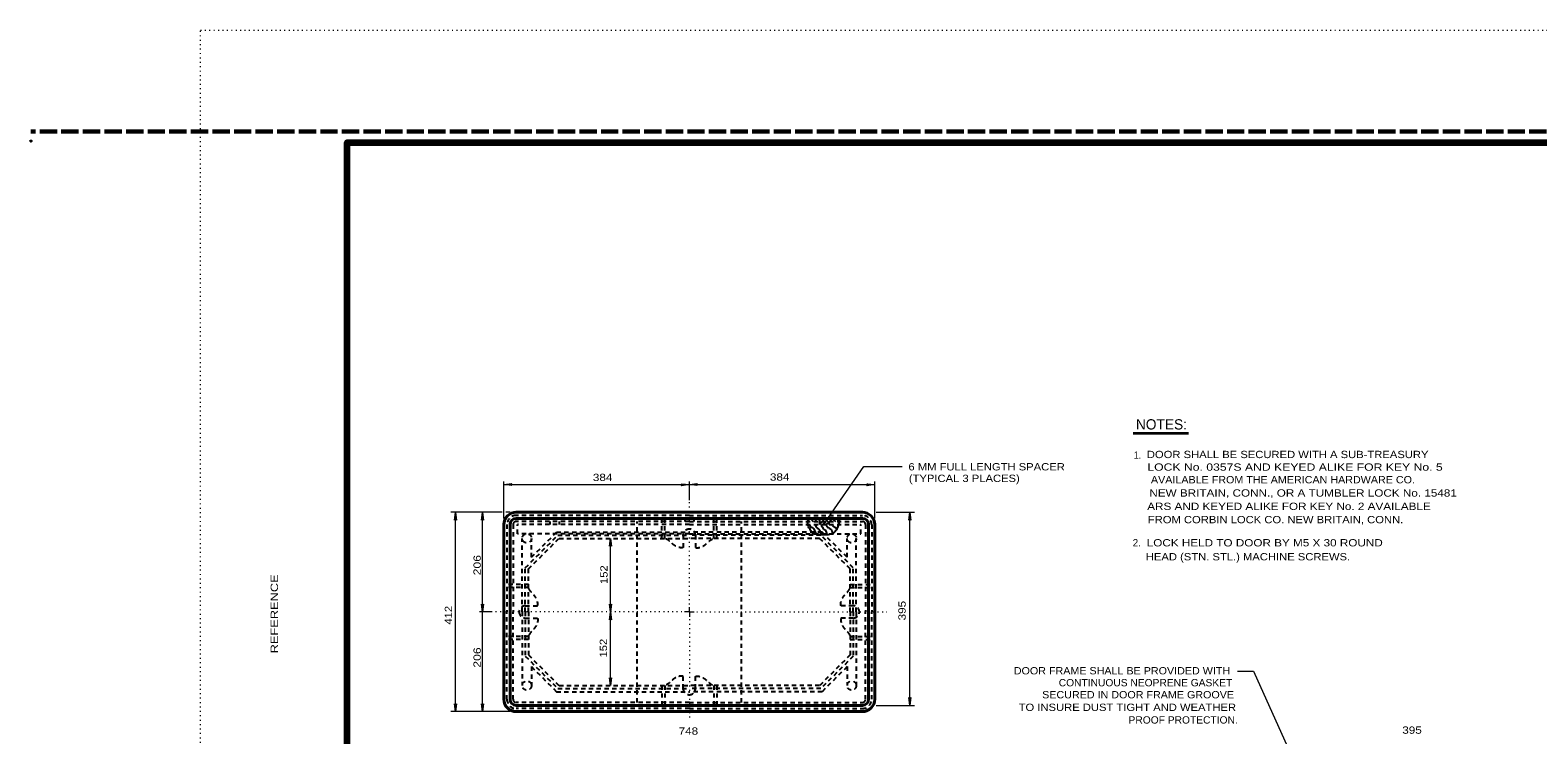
# Model space of a CAD drawing. Extents: x 312583 to 312854, y 144419 to 144597.
# Drawn here: x 312583.5 to 312740.6, y 144523.4 to 144596.8 of the extents above; entities that cross this region are included whole.
import ezdxf
from ezdxf.enums import TextEntityAlignment as Align

# ---------------------------------------------------------------- set-up
doc = ezdxf.new("R2010")
doc.units = 0
doc.header["$LTSCALE"] = 0.3
doc.header["$PDMODE"] = 32
doc.header["$PDSIZE"] = 0.15
for name, pattern in [('DOTTED', [1.5, 0.3, -1.2]), ('LONG_DASHED', [7.5, 6, -1.5]), ('SHORT_DASHED', [2.7, 1.5, -1.2])]:
    doc.linetypes.add(name, pattern=pattern)
for name, color, linetype, lineweight in [('1', 7, 'Continuous', 25), ('2', 7, 'Continuous', 13), ('63', 7, 'DOTTED', 13)]:
    doc.layers.add(name, color=color, linetype=linetype, lineweight=lineweight)

msp = doc.modelspace()

# ---------------------------------------------------------------- linework, layer by layer
at = {"layer": '1', "linetype": 'DOTTED', "lineweight": 13}
msp.add_line((312601.2, 144418.5846), (312601.2, 144596.7846), dxfattribs=at)
at = {"layer": '1', "linetype": 'LONG_DASHED', "lineweight": 60}
msp.add_line((312851.75, 144586.2246), (312583.526, 144586.2246), dxfattribs=at)
at = {"layer": '1', "lineweight": 40}
for p, q in [((312652.1571, 144546.558), (312634.1021, 144546.558)), ((312652.1571, 144545.914), (312634.1021, 144545.914)), ((312652.1571, 144546.558), (312670.2044, 144546.558)), ((312652.1571, 144545.914), (312670.2044, 144545.914)), ((312632.8294, 144545.2777), (312632.8294, 144536.1697)), ((312633.4658, 144545.2777), (312633.4658, 144536.1697)), ((312670.8408, 144545.2777), (312670.8408, 144536.1697)), ((312671.4771, 144545.2777), (312671.4771, 144536.1697)), ((312632.8294, 144527.0693), (312632.8294, 144536.1697)), ((312633.4658, 144527.0693), (312633.4658, 144536.1697)), ((312670.8408, 144527.0693), (312670.8408, 144536.1697)), ((312671.4771, 144527.0693), (312671.4771, 144536.1697)), ((312652.1571, 144526.433), (312634.1021, 144526.433)), ((312652.1571, 144525.789), (312634.1021, 144525.789)), ((312652.1571, 144526.433), (312670.2044, 144526.433)), ((312652.1571, 144525.789), (312670.2044, 144525.789))]:
    msp.add_line(p, q, dxfattribs=at)
at = {"layer": '1', "linetype": 'SHORT_DASHED'}
for p, q in [((312652.1571, 144546.236), (312634.1021, 144546.236)), ((312649.2821, 144543.8363), (312649.2821, 144546.236)), ((312649.5964, 144543.8363), (312649.5964, 144546.236)), ((312651.6741, 144545.914), (312651.6741, 144545.5997)), ((312652.1571, 144546.236), (312670.2044, 144546.236)), ((312652.6324, 144545.914), (312652.6324, 144545.5997)), ((312654.7101, 144543.8363), (312654.7101, 144546.236)), ((312655.0321, 144543.8363), (312655.0321, 144546.236)), ((312633.1438, 144545.2777), (312633.1438, 144536.1697)), ((312633.7878, 144545.2777), (312633.7878, 144536.1697)), ((312652.1571, 144545.5997), (312634.1021, 144545.5997)), ((312652.1571, 144545.2777), (312634.2631, 144545.2777)), ((312635.7044, 144541.866), (312638.3111, 144544.4803)), ((312637.6211, 144545.5997), (312637.6211, 144545.2777)), ((312638.3111, 144544.4803), (312652.1571, 144544.4803)), ((312638.5794, 144545.5997), (312638.5794, 144545.2777)), ((312646.7214, 144526.7473), (312646.7214, 144545.5997)), ((312652.1571, 144545.5997), (312670.2044, 144545.5997)), ((312652.1571, 144545.2777), (312670.0434, 144545.2777)), ((312665.9954, 144544.4803), (312652.1571, 144544.4803)), ((312657.5851, 144526.7473), (312657.5851, 144545.5997)), ((312665.7271, 144545.5997), (312665.7271, 144545.2777)), ((312668.6021, 144541.866), (312665.9954, 144544.4803)), ((312666.6854, 144545.5997), (312666.6854, 144545.2777)), ((312670.5188, 144545.2777), (312670.5188, 144536.1697)), ((312671.1628, 144545.2777), (312671.1628, 144536.1697)), ((312634.7461, 144536.1697), (312634.7461, 144543.8363)), ((312635.7044, 144541.866), (312635.7044, 144543.8363)), ((312638.5794, 144543.8363), (312652.1571, 144543.8363)), ((312651.5131, 144544.1583), (312651.5131, 144542.878)), ((312665.7271, 144543.8363), (312652.1571, 144543.8363)), ((312652.7934, 144544.1583), (312652.7934, 144542.878)), ((312668.6021, 144541.866), (312668.6021, 144543.8363)), ((312669.5604, 144536.1697), (312669.5604, 144543.8363)), ((312635.3824, 144539.0447), (312633.1438, 144539.0447)), ((312635.3824, 144538.7303), (312633.1438, 144538.7303)), ((312668.9241, 144539.0447), (312671.1628, 144539.0447)), ((312668.9241, 144538.7303), (312671.1628, 144538.7303)), ((312635.0604, 144536.8137), (312636.3408, 144536.8137)), ((312669.2461, 144536.8137), (312667.9658, 144536.8137)), ((312633.1438, 144527.0693), (312633.1438, 144536.1697)), ((312633.7878, 144527.0693), (312633.7878, 144536.1697)), ((312634.7461, 144536.1697), (312634.7461, 144528.503)), ((312635.0604, 144535.5333), (312636.3408, 144535.5333)), ((312669.2461, 144535.5333), (312667.9658, 144535.5333)), ((312669.5604, 144536.1697), (312669.5604, 144528.503)), ((312670.5188, 144527.0693), (312670.5188, 144536.1697)), ((312671.1628, 144527.0693), (312671.1628, 144536.1697)), ((312635.3824, 144533.6167), (312633.1438, 144533.6167)), ((312635.3824, 144533.2947), (312633.1438, 144533.2947)), ((312668.9241, 144533.6167), (312671.1628, 144533.6167)), ((312668.9241, 144533.2947), (312671.1628, 144533.2947)), ((312635.7044, 144530.4733), (312635.7044, 144528.503)), ((312635.7044, 144530.4733), (312638.3111, 144527.8667)), ((312668.6021, 144530.4733), (312665.9954, 144527.8667)), ((312668.6021, 144530.4733), (312668.6021, 144528.503)), ((312638.5794, 144528.503), (312652.1571, 144528.503)), ((312649.2821, 144528.503), (312649.2821, 144526.111)), ((312649.5964, 144528.503), (312649.5964, 144526.111)), ((312651.5131, 144528.1887), (312651.5131, 144529.4613)), ((312665.7271, 144528.503), (312652.1571, 144528.503)), ((312652.7934, 144528.1887), (312652.7934, 144529.4613)), ((312654.7101, 144528.503), (312654.7101, 144526.111)), ((312655.0321, 144528.503), (312655.0321, 144526.111)), ((312638.3111, 144527.8667), (312652.1571, 144527.8667)), ((312665.9954, 144527.8667), (312652.1571, 144527.8667)), ((312652.1571, 144526.7473), (312634.1021, 144526.7473)), ((312652.1571, 144526.111), (312634.1021, 144526.111)), ((312652.1571, 144526.7473), (312670.2044, 144526.7473)), ((312652.1571, 144526.111), (312670.2044, 144526.111))]:
    msp.add_line(p, q, dxfattribs=at)
at = {"layer": '1'}
for p, q in [((312664.5158, 144545.7837), (312664.6921, 144545.5997)), ((312664.7841, 144545.914), (312665.0754, 144545.5997)), ((312665.1674, 144545.914), (312665.4588, 144545.5997)), ((312665.5508, 144545.914), (312665.8421, 144545.5997)), ((312665.9341, 144545.914), (312666.2254, 144545.5997)), ((312666.3174, 144545.914), (312666.6088, 144545.5997)), ((312666.7008, 144545.914), (312666.9921, 144545.5997)), ((312667.0841, 144545.914), (312667.3754, 144545.5997)), ((312667.4674, 144545.914), (312667.7588, 144545.5997)), ((312665.7271, 144545.3083), (312666.0491, 144545.5997)), ((312666.0798, 144545.2777), (312666.4324, 144545.5997)), ((312666.4631, 144545.2777), (312666.6854, 144545.4847))]:
    msp.add_line(p, q, dxfattribs=at)
at = {"layer": '1', "lineweight": 158}
msp.add_lwpolyline([(312616.5, 144423.1446), (312616.5, 144585.0846), (312849, 144585.0846)], dxfattribs=at)
at = {"layer": '1', "linetype": 'SHORT_DASHED'}
for points in [[(312652.1571, 144544.3193), (312634.2631, 144544.3193), (312634.2631, 144545.2777)], [(312652.1571, 144544.3193), (312670.0434, 144544.3193), (312670.0434, 144545.2777)], [(312635.0604, 144536.1697), (312635.0604, 144540.7773), (312638.4414, 144544.1583), (312652.1571, 144544.1583)], [(312635.3824, 144536.1697), (312635.3824, 144540.647), (312638.5794, 144543.8363)], [(312669.2461, 144536.1697), (312669.2461, 144540.7773), (312665.8651, 144544.1583), (312652.1571, 144544.1583)], [(312668.9241, 144536.1697), (312668.9241, 144540.647), (312665.7271, 144543.8363)], [(312635.0604, 144536.1697), (312635.0604, 144531.5697), (312638.4414, 144528.1887), (312652.1571, 144528.1887)], [(312635.3824, 144536.1697), (312635.3824, 144531.7), (312638.5794, 144528.503)], [(312669.2461, 144536.1697), (312669.2461, 144531.5697), (312665.8651, 144528.1887), (312652.1571, 144528.1887)], [(312668.9241, 144536.1697), (312668.9241, 144531.7), (312665.7271, 144528.503)]]:
    msp.add_lwpolyline(points, dxfattribs=at)
for centre in [(312635.2227, 144543.8402), (312669.0838, 144543.8402), (312635.2227, 144528.5068), (312669.0838, 144528.5068)]:
    msp.add_circle(centre, 0.4792, dxfattribs=at)
at = {"layer": '1', "lineweight": 40}
for centre, radius, start, end in [((312634.1047, 144545.2777), 1.2778, 90, 180), ((312634.1047, 144545.2777), 0.6389, 90, 180), ((312670.2019, 144545.2777), 1.2778, 0, 90), ((312670.2019, 144545.2777), 0.6389, 0, 90), ((312634.1047, 144527.0693), 1.2778, 180, 270), ((312634.1047, 144527.0693), 0.6389, 180, 270), ((312670.2019, 144527.0693), 1.2778, 270, 0), ((312670.2019, 144527.0693), 0.6389, 270, 0)]:
    msp.add_arc(centre, radius, start, end, dxfattribs=at)
at = {"layer": '1', "linetype": 'SHORT_DASHED'}
for centre, radius, start, end in [((312634.1047, 144545.2777), 0.9583, 90, 180), ((312670.2019, 144545.2777), 0.9583, 0, 90), ((312634.1047, 144545.2777), 0.3194, 90, 180), ((312652.1533, 144544.1596), 0.6389, 90, 180), ((312652.1533, 144544.1596), 0.6389, 0, 90), ((312670.2019, 144545.2777), 0.3194, 0, 90), ((312635.063, 144536.1735), 0.6389, 90, 180), ((312669.2435, 144536.1735), 0.6389, 0, 90), ((312635.063, 144536.1735), 0.6389, 180, 270), ((312669.2435, 144536.1735), 0.6389, 270, 0), ((312634.1047, 144527.0693), 0.9583, 180, 270), ((312634.1047, 144527.0693), 0.3194, 180, 270), ((312652.1533, 144528.1874), 0.6389, 180, 270), ((312652.1533, 144528.1874), 0.6389, 270, 0), ((312670.2019, 144527.0693), 0.9583, 270, 0), ((312670.2019, 144527.0693), 0.3194, 270, 0)]:
    msp.add_arc(centre, radius, start, end, dxfattribs=at)
at = {"layer": '1'}
for points in [[(312667.7971, 144545.9063), (312667.7741, 144545.684), (312667.6591, 144545.1857), (312667.4904, 144544.741), (312667.1684, 144544.396), (312666.9078, 144544.281), (312666.3634, 144544.1967), (312665.8804, 144544.212), (312665.3974, 144544.2503), (312665.0601, 144544.35), (312664.7381, 144544.7487), (312664.5464, 144545.1627), (312664.5158, 144545.477), (312664.5311, 144545.6533), (312664.4698, 144545.9217)], [(312664.6691, 144545.2777), (312664.7074, 144545.1933), (312664.7841, 144545.0477), (312664.8914, 144544.994), (312665.0524, 144544.9173), (312665.1828, 144544.7103), (312665.2364, 144544.5723), (312665.2978, 144544.4113), (312665.3591, 144544.3193)], [(312665.2441, 144545.2623), (312665.2901, 144545.178), (312665.3821, 144545.0093), (312665.5354, 144544.8713), (312665.6658, 144544.7563), (312665.7578, 144544.5953), (312665.8114, 144544.4573), (312665.9034, 144544.3347)], [(312665.8574, 144545.27), (312665.8958, 144545.2087), (312665.9878, 144545.0553), (312666.0644, 144544.925), (312666.2254, 144544.7793), (312666.3634, 144544.6567), (312666.4248, 144544.488), (312666.4554, 144544.3807), (312666.4631, 144544.3193)], [(312666.4018, 144545.2777), (312666.4401, 144545.1473), (312666.5551, 144545.017), (312666.7238, 144544.9173), (312666.8848, 144544.81), (312667.0228, 144544.603), (312667.0458, 144544.5187), (312667.1224, 144544.3807)], [(312667.0381, 144545.27), (312667.0841, 144545.1933), (312667.1761, 144545.0937), (312667.3141, 144545.0093), (312667.4368, 144544.9403), (312667.5364, 144544.833)]]:
    msp.add_spline(points, degree=3, dxfattribs=at)
at = {"layer": '1', "linetype": 'SHORT_DASHED'}
for points in [[(312651.5131, 144542.878), (312651.2601, 144542.8627), (312650.8768, 144542.9623), (312650.5088, 144543.1693), (312650.1868, 144543.453), (312649.9414, 144543.66), (312649.5964, 144543.8363)], [(312652.7934, 144542.878), (312653.0464, 144542.8627), (312653.4298, 144542.9623), (312653.7978, 144543.1693), (312654.1198, 144543.453), (312654.3651, 144543.66), (312654.7101, 144543.8363)], [(312636.3408, 144536.8137), (312636.3561, 144537.0667), (312636.2641, 144537.45), (312636.0494, 144537.818), (312635.7734, 144538.14), (312635.5588, 144538.3853), (312635.3824, 144538.7303)], [(312667.9658, 144536.8137), (312667.9504, 144537.0667), (312668.0424, 144537.45), (312668.2571, 144537.818), (312668.5331, 144538.14), (312668.7478, 144538.3853), (312668.9241, 144538.7303)], [(312636.3408, 144535.5333), (312636.3561, 144535.2803), (312636.2641, 144534.897), (312636.0494, 144534.529), (312635.7734, 144534.207), (312635.5588, 144533.9617), (312635.3824, 144533.6167)], [(312667.9658, 144535.5333), (312667.9504, 144535.2803), (312668.0424, 144534.897), (312668.2571, 144534.529), (312668.5331, 144534.207), (312668.7478, 144533.9617), (312668.9241, 144533.6167)], [(312651.5131, 144529.4613), (312651.2601, 144529.4843), (312650.8768, 144529.3847), (312650.5088, 144529.1777), (312650.1868, 144528.894), (312649.9414, 144528.687), (312649.5964, 144528.503)], [(312652.7934, 144529.4613), (312653.0464, 144529.4843), (312653.4298, 144529.3847), (312653.7978, 144529.1777), (312654.1198, 144528.894), (312654.3651, 144528.687), (312654.7101, 144528.503)]]:
    msp.add_spline(points, degree=3, dxfattribs=at)
at = {"layer": '1'}
msp.add_point((312583.526, 144585.2246), dxfattribs=at)
at = {"layer": '2', "lineweight": 35}
msp.add_line((312698.4305, 144554.8026), (312704.1757, 144554.8026), dxfattribs=at)
at = {"layer": '2'}
for p, q in [((312666.3558, 144545.5767), (312670.3501, 144551.319)), ((312670.3501, 144551.319), (312674.3521, 144551.319)), ((312632.8294, 144545.914), (312632.8294, 144549.7473)), ((312632.8294, 144549.433), (312652.1571, 144549.433)), ((312652.1571, 144547.8307), (312652.1571, 144549.7473)), ((312652.1571, 144549.433), (312671.4771, 144549.433)), ((312671.4771, 144545.914), (312671.4771, 144549.7473)), ((312632.6608, 144546.558), (312627.3018, 144546.558)), ((312627.7771, 144525.789), (312627.7771, 144546.558)), ((312633.4658, 144546.558), (312633.0134, 144546.558)), ((312671.6458, 144546.558), (312675.6171, 144546.558)), ((312675.1418, 144526.433), (312675.1418, 144546.558)), ((312652.1571, 144536.1697), (312652.1571, 144536.6833)), ((312631.5491, 144536.1697), (312630.2688, 144536.1697)), ((312652.1571, 144536.1697), (312651.6434, 144536.1697)), ((312652.1571, 144536.1697), (312652.1571, 144535.6637)), ((312652.1571, 144536.1697), (312652.6631, 144536.1697)), ((312633.4658, 144525.789), (312627.3018, 144525.789)), ((312671.6458, 144526.433), (312675.6171, 144526.433))]:
    msp.add_line(p, q, dxfattribs=at)
at = {"layer": '2', "linetype": 'DOTTED'}
for p, q in [((312652.1571, 144536.9363), (312652.1571, 144547.8307)), ((312651.3904, 144536.1697), (312631.5491, 144536.1697)), ((312652.1571, 144535.403), (312652.1571, 144525.0223)), ((312652.9238, 144536.1697), (312672.7574, 144536.1697))]:
    msp.add_line(p, q, dxfattribs=at)
at = {"layer": '2'}
for points in [[(312633.6427, 144549.3336), (312632.8294, 144549.433), (312633.6427, 144549.5414), (312633.5613, 144549.433)], [(312651.3438, 144549.5324), (312652.1571, 144549.433), (312651.3438, 144549.3246), (312651.4252, 144549.433)], [(312652.9704, 144549.3336), (312652.1571, 144549.433), (312652.9704, 144549.5414), (312652.889, 144549.433)], [(312670.6638, 144549.5324), (312671.4771, 144549.433), (312670.6638, 144549.3246), (312670.7452, 144549.433)], [(312627.6777, 144545.7447), (312627.7771, 144546.558), (312627.8855, 144545.7447), (312627.7771, 144545.8261)], [(312630.4914, 144545.7447), (312630.5908, 144546.558), (312630.6992, 144545.7447), (312630.5908, 144545.8261)], [(312666.6624, 144545.9217), (312666.3558, 144545.5767), (312666.5704, 144545.9907), (312666.5934, 144545.9217)], [(312675.0424, 144545.7447), (312675.1418, 144546.558), (312675.2502, 144545.7447), (312675.1418, 144545.8261)], [(312643.839, 144543.023), (312643.9384, 144543.8363), (312644.0468, 144543.023), (312643.9384, 144543.1044)], [(312630.6902, 144536.983), (312630.5908, 144536.1697), (312630.4824, 144536.983), (312630.5908, 144536.9016)], [(312644.0378, 144536.983), (312643.9384, 144536.1697), (312643.83, 144536.983), (312643.9384, 144536.9016)], [(312643.839, 144535.3564), (312643.9384, 144536.1697), (312644.0468, 144535.3564), (312643.9384, 144535.4378)], [(312644.0378, 144529.3163), (312643.9384, 144528.503), (312643.83, 144529.3163), (312643.9384, 144529.2349)], [(312675.2412, 144527.2463), (312675.1418, 144526.433), (312675.0334, 144527.2463), (312675.1418, 144527.1649)], [(312627.8765, 144526.6023), (312627.7771, 144525.789), (312627.6687, 144526.6023), (312627.7771, 144526.5209)], [(312630.6902, 144526.6023), (312630.5908, 144525.789), (312630.4824, 144526.6023), (312630.5908, 144526.5209)]]:
    msp.add_lwpolyline(points, close=True, dxfattribs=at)
for points in [[(312630.5908, 144525.789), (312630.5908, 144536.1697), (312630.5908, 144546.558)], [(312643.9384, 144528.503), (312643.9384, 144536.1697), (312643.9384, 144543.8363)], [(312709.3044, 144530.0133), (312710.9528, 144530.0133), (312718.1211, 144514.082)]]:
    msp.add_lwpolyline(points, dxfattribs=at)
at = {"layer": '63'}
msp.add_line((312601.2, 144596.7846), (312853.5, 144596.7846), dxfattribs=at)

# ---------------------------------------------------------------- texts
at = {"layer": '1', "width": 1.3}
msp.add_text('REFERENCE                                                              ', height=0.7682, rotation=90, dxfattribs=at).set_placement((312609.2854, 144531.8549))
at = {"layer": '2'}
for s, height, p in [('NOTES:', 1.07, (312701.3643, 144555.181)), ('2.', 0.76, (312698.7921, 144542.9988))]:
    msp.add_text(s, height=height, dxfattribs=at).set_placement(p, align=Align.CENTER)
for s, width, p in [('1.', 0.9, (312698.8622, 144552.1296)), ('DOOR SHALL BE SECURED WITH A SUB-TREASURY', 1.15, (312714.517, 144552.1997)), ('384 ', 1.2, (312643.289, 144549.8108)), ('384 ', 1.2, (312661.7436, 144549.8488)), ('6 MM FULL LENGTH SPACER', 1.15, (312683.1431, 144550.9162)), ('(TYPICAL 3 PLACES)', 1.15, (312680.8169, 144549.7131)), ('LOCK No. 0357S AND KEYED ALIKE FOR KEY No. 5', 1.25, (312715.2876, 144550.8858)), ('NEW BRITAIN, CONN., OR A TUMBLER LOCK No. 15481', 1.2, (312716.1284, 144548.1875)), ('AVAILABLE FROM THE AMERICAN HARDWARE CO.', 1.1, (312714.0265, 144549.5718)), ('ARS AND KEYED ALIKE FOR KEY No. 2 AVAILABLE', 1.2, (312714.657, 144546.7957)), ('FROM CORBIN LOCK CO. NEW BRITAIN, CONN.', 1.15, (312713.2558, 144545.4115)), ('LOCK HELD TO DOOR BY M5 X 30 ROUND', 1.2, (312712.1309, 144542.9988)), ('HEAD (STN. STL.) MACHINE SCREWS.', 1.15, (312710.3834, 144541.5445)), ('DOOR FRAME SHALL BE PROVIDED WITH', 1.1, (312697.2495, 144529.6666)), ('CONTINUOUS NEOPRENE GASKET', 1.05, (312699.7016, 144528.4229)), ('SECURED IN DOOR FRAME GROOVE', 1.1, (312698.9311, 144527.1712)), ('TO INSURE DUST TIGHT AND WEATHER', 1.15, (312697.81, 144525.8573)), ('748 ', 1.2, (312652.2268, 144523.3835)), ('PROOF PROTECTION.', 1.05, (312703.6251, 144524.5432)), ('395 ', 1.2, (312727.6515, 144523.4803))]:
    msp.add_text(s, height=0.76, dxfattribs=dict(at, width=width)).set_placement(p, align=Align.CENTER)
for s, width, p in [('206 ', 1.25, (312630.4178, 144541.2228)), ('152 ', 1.15, (312643.6374, 144540.2193)), ('412 ', 1.15, (312627.4235, 144535.9914)), ('395 ', 1.2, (312674.7049, 144536.4782)), ('152 ', 1.15, (312643.5762, 144532.5638)), ('206 ', 1.25, (312630.4178, 144531.5983))]:
    msp.add_text(s, height=0.76, rotation=90, dxfattribs=dict(at, width=width)).set_placement(p, align=Align.CENTER)

doc.saveas('drawing.dxf')
